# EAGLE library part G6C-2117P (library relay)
RELAY 1 x norm. open, 1x norm. closed, 10 A/240 V, Omron
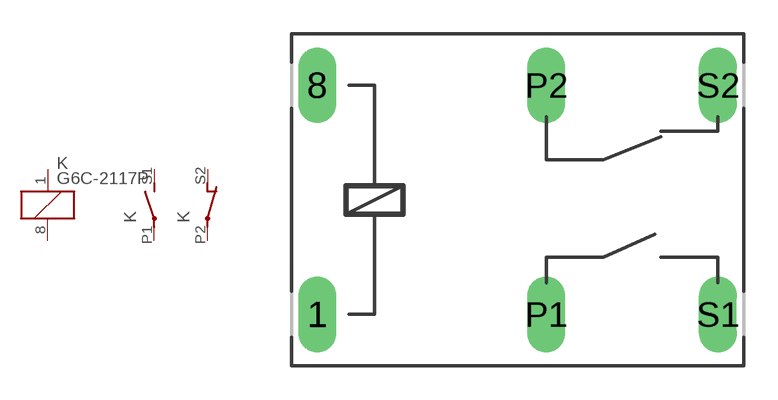
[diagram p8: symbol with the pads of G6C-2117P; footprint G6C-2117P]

Designator prefix K; gates 1=K 2=S 3=O

## G6C-2117P (OC_FARNELL: unknown; OC_NEWARK: unknown)  [G6C-2117P]
1  1:1  pas
8  1:2  pas
P1  2:P  pas
P2  3:P  pas
S1  2:S  pas
S2  3:O  pas

## Footprint G6C-2117P (pad centres in mm)
RELAY 1 x norm. open, 1x norm. closed, 10 A/240 V, Omron
drill 1.118 long: 1 -8.89,-5.08; 8 -8.89,5.08; P1 1.27,-5.08; P2 1.27,5.08; S1 8.89,-5.08; S2 8.89,5.08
